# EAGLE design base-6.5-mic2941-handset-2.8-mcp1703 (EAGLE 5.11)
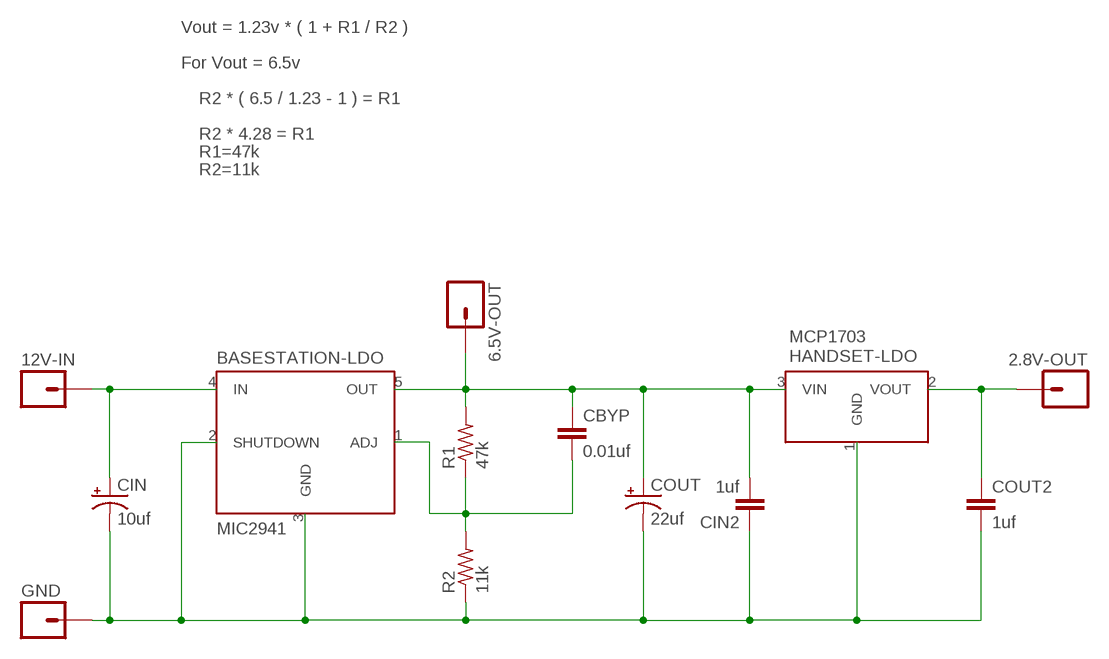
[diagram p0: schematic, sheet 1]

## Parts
2.8V-OUT  M01PTH_LONGPAD  [1X01_LONGPAD]
6.5V-OUT  M01PTH_LONGPAD  [1X01_LONGPAD]
12V-IN  M01PTH_LONGPAD  [1X01_LONGPAD]
BASESTATION-LDO  MIC2941  [TO-220-5]
CBYP  0.01uf  C-EUC1206  [C1206]
CIN  10uf  CPOL-USE2-5  [E2-5]
CIN2  1uf  C-EUC1206  [C1206]
COUT  22uf  CPOL-USE2-5  [E2-5]
COUT2  1uf  C-EUC1206  [C1206]
GND  M01PTH_LONGPAD  [1X01_LONGPAD]
HANDSET-LDO  MCP1703  [SOT23-3]
R1  47k  R-US_R0805  [R0805]
R2  11k  R-US_R0805  [R0805]

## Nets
ADJ: BASESTATION-LDO.1(ADJ) CBYP.2 R1.1 R2.2
GND: BASESTATION-LDO.2(SHUTDOWN) BASESTATION-LDO.3(GND) CIN2.1 CIN.- COUT2.2 COUT.- GND.1 HANDSET-LDO.1(GND) R2.1
VIN: 12V-IN.1 BASESTATION-LDO.4(IN) CIN.+
VOUT: 6.5V-OUT.1 BASESTATION-LDO.5(OUT) CBYP.1 CIN2.2 COUT.+ HANDSET-LDO.3(VIN) R1.2
VOUT2: 2.8V-OUT.1 COUT2.1 HANDSET-LDO.2(VOUT)

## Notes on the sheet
- Vout = 1.23v * ( 1 + R1 / R2 )
- For Vout = 6.5v
- R2 * ( 6.5 / 1.23 - 1 ) = R1
- R2 * 4.28 = R1
- R1=47k
- R2=11k

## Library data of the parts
2.8V-OUT 6.5V-OUT 12V-IN GND = SparkFun2011-02-20:M01: Header 1
BASESTATION-LDO = trl:MIC2941
CBYP CIN2 COUT2 = rcl:C-EU: CAPACITOR, European symbol
CIN COUT = rcl:CPOL-US: POLARIZED CAPACITOR, American symbol
HANDSET-LDO = trl:MCP1703
R1 R2 = resistor:R-US_: RESISTOR, American symbol

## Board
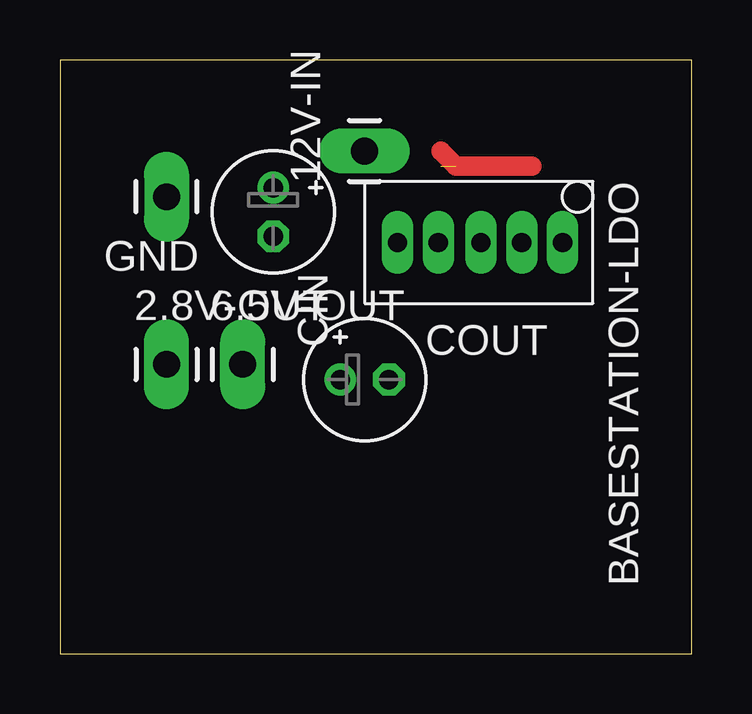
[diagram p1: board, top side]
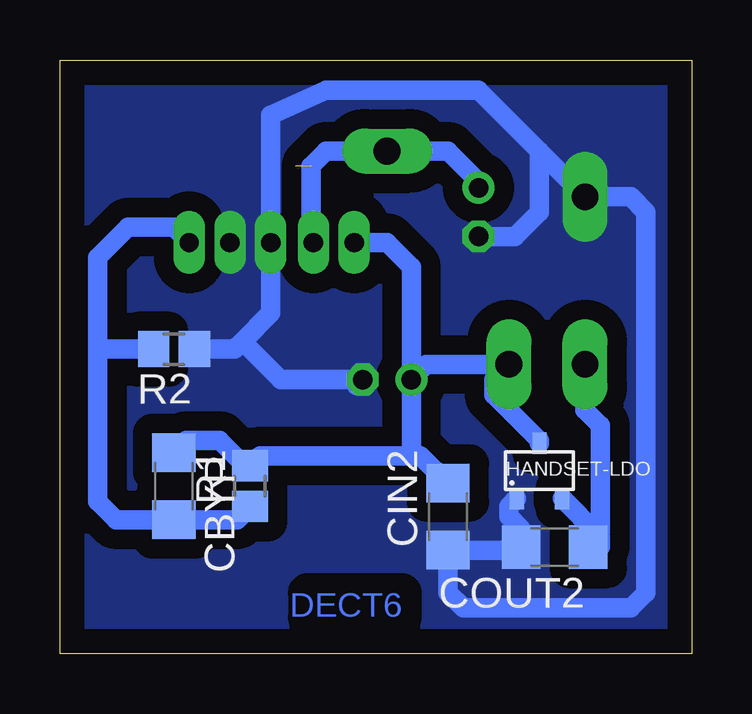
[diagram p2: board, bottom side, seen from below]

Size 26.34 x 24.75 mm. Coordinates in mm from the lower left corner, seen from the top.
Outline: 0,0 26.34,0 26.34,24.75 0,24.75 0,0
Copper layers (1*16): Top 0.035mm / dielectric 1.5mm / Bottom 0.035mm
Design rules "default": minimum track width 10mil, minimum drill 24mil, track to track 8mil, track to pad 8mil, pad to pad 8mil, via to via 8mil, smd to smd 8mil, copper to edge 40mil, drill to drill 8mil, minimum pad ring 10mil, minimum via ring 8mil, stop-mask expansion 4mil, vias tented up to drill 0mil, thermal gap 10mil

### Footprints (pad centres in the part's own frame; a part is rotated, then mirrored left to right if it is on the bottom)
1X01_LONGPAD = drill 1.118 pad 1.88 long: 1 0,0
TO-220-5 = drill 0.8 long: 1 -3.81,0; 2 -2.108,0; 3 -0.406,0; 4 1.372,0; 5 3.073,0
C1206 = smd 1.6 x 1.8: 1 -1.4,0; 2 1.4,0
E2-5 = drill 0.813 pad 1.27 round: + -1.016,0 | drill 0.813 pad 1.27 octagon: - 1.016,0
SOT23-3 = smd 0.6 x 0.9: 1 -0.95,-1.15; 2 0.95,-1.15; 3 0,1.15
R0805 = smd 1.3 x 1.5: 1 -0.85,0; 2 0.85,0

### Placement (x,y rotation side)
2.8V-OUT  4.45,12.06 0 top
6.5V-OUT  7.62,12.06 0 top
12V-IN  12.7,20.95 90 top
BASESTATION-LDO  17.14,17.14 180 top
CBYP  21.59,6.99 270 bottom
CIN  8.89,18.41 270 top
CIN2  10.16,5.71 90 bottom
COUT  12.7,11.43 0 top
COUT2  5.71,4.45 180 bottom
GND  4.45,19.05 180 top
HANDSET-LDO  6.35,7.62 0 bottom
R1  18.41,6.99 90 bottom
R2  21.59,12.7 180 bottom

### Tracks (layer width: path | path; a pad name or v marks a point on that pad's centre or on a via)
ADJ
  Bottom 0.813: R1.1 18.96,5.58 CBYP.2 24,5.58 24.77,6.35 24.77,12.7 | 24.77,12.7 24.77,16.51 23.5,17.78 21.59,17.78 BASESTATION-LDO.1 | 24.77,12.7 R2.2
GND
  Bottom 0.813: 18.73,13.02 17.55,14.2 BASESTATION-LDO.3 17.55,22.45 15.24,23.5 8.89,23.5 6.35,20.95 | 18.73,13.02 19.05,12.7 R2.1 | 18.73,13.02 17.14,11.43 COUT.- 13.97,11.18 | CIN.- 7.37,17.4 6.35,18.41 6.35,20.95 | 6.35,20.95 GND.1 2.54,19.05 1.91,18.41 1.91,2.54 2.54,1.91 9.53,1.91 10.16,2.54 CIN2.1 7.25,4.32 COUT2.2 7.12,5.21 7.62,5.71 7.62,6.15 HANDSET-LDO.1
  pour Bottom (isolate 0.813, no thermals): 0,24.77 26.04,24.77 26.04,0 0,0
VIN  (1 unrouted)
  Top 0.813: 19.68,20.32 16.51,20.32 15.88,20.95
  Bottom 0.813: CIN.+ 8.89,19.68 10.16,20.95 12V-IN.1 15.24,20.95 15.88,20.32 15.88,17.25 BASESTATION-LDO.4
VOUT
  Bottom 0.813: BASESTATION-LDO.5 12.7,17.14 11.68,16.13 COUT.+ | CBYP.1 21.09,8.89 19.68,8.89 18.63,7.83 R1.2 18,8.26 11.43,8.26 | HANDSET-LDO.3 6.35,8.89 8.26,10.79 8.26,11.43 6.5V-OUT.1 11.05,12.06 COUT.+ | 11.43,8.26 11.3,8.26 CIN2.2 | COUT.+ 11.68,8.51 11.43,8.26
VOUT2
  Bottom 0.813: COUT2.1 3.81,4.45 3.81,4.88 3.91,4.98 | 3.91,4.98 HANDSET-LDO.2 | 2.8V-OUT.1 4.45,10.16 3.81,9.53 3.81,5.08 3.91,4.98

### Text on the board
Bottom: DECT6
